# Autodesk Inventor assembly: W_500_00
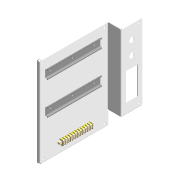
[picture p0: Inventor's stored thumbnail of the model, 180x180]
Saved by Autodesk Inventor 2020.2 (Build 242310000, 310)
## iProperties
Created: 2015-10
Part Number: W_500_00
Document SubType Name: Assembly
Designer: F.Stasiak
Catalog Web Link: www.expertbooks.pl
Manager: www.cadconsulting.pl
Company: Fabian Stasiak CAD Consulting
Author: F.Stasiak
Subject: Zbiór ćwiczeń. Autodesk Inventor 2020. Kurs Professional
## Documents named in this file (4)
- C:\2020_Kurs_Professional\R2 Wiązki\W_500_00.iam
- C:\2020_Kurs_Professional\R2 Wiązki\Komponenty\W_500_01.ipt
- C:\2020_Kurs_Professional\R2 Wiązki\Komponenty\DIN35_EN50022_200.ipt
- C:\2020_Kurs_Professional\R2 Wiązki\Komponenty\LISTWA_100_01.ipt
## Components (4 placed, 3 different names)
1. W_500_01:1 — Zestawiający:1, Wstaw:1, Wstaw:2, Wstaw:3, Wstaw:4, Wstaw:5, Wstaw:6
2. DIN35_EN50022_200:1 — Zestawiający:1, Wstaw:1, Wstaw:2
3. DIN35_EN50022_200:2 — Wstaw:3, Wstaw:4
4. LISTWA_100_01:1 — Wstaw:5, Wstaw:6
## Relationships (7: Insert 6, Mate 1)
- Zestawiający:1 [Mate]: W_500_01:1 ↔ DIN35_EN50022_200:1
- Wstaw:1 [Insert]: W_500_01:1 ↔ DIN35_EN50022_200:1
- Wstaw:2 [Insert]: W_500_01:1 ↔ DIN35_EN50022_200:1
- Wstaw:3 [Insert]: W_500_01:1 ↔ DIN35_EN50022_200:2
- Wstaw:4 [Insert]: W_500_01:1 ↔ DIN35_EN50022_200:2
- Wstaw:5 [Insert]: W_500_01:1 ↔ LISTWA_100_01:1
- Wstaw:6 [Insert]: W_500_01:1 ↔ LISTWA_100_01:1
